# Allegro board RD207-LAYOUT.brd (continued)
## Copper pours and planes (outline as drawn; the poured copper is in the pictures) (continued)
N17056068 on TOP: 49.06,31 49,31.01 48.96,31.04 47.75,32.25 47.52,32.38 47.39,32.4 46.15,32.4 46.04,32.44 46,32.55 46,32.8 45.82,33.22 45.4,33.4 44.6,33.4 44.18,33.22 44,32.8 44,32.55 43.96,32.44 43.85,32.4 42.55,32.4 42.44,32.44 42.4,32.55 42.4,33.6 42.44,33.71 42.55,33.75 43.2,33.75 43.6,33.86 43.89,34.15 44,34.55 44,36.1 44.04,36.21 44.15,36.25 45.54,36.25 46.12,36.36 46.6,36.69 48.81,38.9 48.82,38.9 49,39.13 49.13,39.38 49.15,39.41 49.22,39.55 49.25,39.71 49.25,42.7 49.4,43.05 49.75,43.2 53.5,43.2 53.85,43.05 54,42.7 54,38.23 53.94,38.11 53.82,38.08 53.73,38.1 53.65,38.1 53.05,38.1 52.48,37.87 52.25,37.3 52.25,34.7 52.48,34.13 53.05,33.9 53.65,33.9 53.73,33.9 53.82,33.92 53.94,33.89 54,33.77 54,31.5 53.85,31.15 53.5,31
N17156262 on TOP: 20.75,68.1 20.66,68.12 20.58,68.17 17.91,70.84 17.83,70.95 17.76,71.2 17.76,79.5 17.83,79.75 18.01,79.93 18.26,80 25.6,80 25.85,79.93 26.03,79.75 26.1,79.5 26.1,71.15 26.02,70.97 25.84,70.9 25.8,70.9 25.6,70.9 25.03,70.67 24.8,70.1 24.8,69.9 25.03,69.33 25.6,69.1 25.8,69.1 25.84,69.1 26.02,69.03 26.1,68.85 26.1,68.6 26.03,68.35 25.85,68.17 25.6,68.1
N17207036 on TOP: 143.54,117.04 143.54,117.08 143.65,117.18 143.8,117.15 143.95,117 143.99,116.89 143.95,116.78 143.8,116.63 143.76,116.61 143.61,116.61 143.54,116.74
N17207036 on TOP: 142.24,115.58 142.22,115.62 142.22,115.77 142.35,115.84 142.65,115.84 142.69,115.84 142.79,115.73 142.76,115.58 142.61,115.43 142.5,115.39 142.39,115.43
N17207166 on TOP: 138.97,115.59 138.95,115.63 138.95,115.78 139.08,115.85 139.38,115.85 139.42,115.85 139.52,115.74 139.49,115.59 139.34,115.44 139.23,115.4 139.12,115.44
N17209635 on TOP: 395.97,234.09 395.95,234.13 395.95,234.28 396.08,234.35 396.38,234.35 396.42,234.35 396.52,234.24 396.49,234.09 396.34,233.94 396.23,233.9 396.12,233.94
N17227344 on TOP (solid shape): 361.53,117.8 362.08,117.55 362.13,116.95 361.95,116.37 361.36,116.24 360.47,116.53 360.06,117.16 360.59,117.7
N17229013 on TOP (solid shape): 361.53,37.3 362.08,37.05 362.13,36.45 361.95,35.87 361.36,35.74 360.47,36.03 360.06,36.66 360.59,37.2
N17284402 on TOP: 284.2,235.59 279.62,238.45 279.59,238.45 271.37,238.45 271.24,238.47 271.01,238.6 270.68,238.93 270.63,239.01 270.61,239.1 270.61,255.4 270.63,255.49 270.68,255.57 280.11,265 280.21,265.07 280.46,265.14 304.24,265.14 304.37,265.12 304.6,265 314.45,255.14 345.83,255.14 346.22,255.06 346.54,254.85 346.76,254.52 346.83,254.14 346.83,249.03 346.82,248.97 346.45,247.92 346.33,246.87 346.33,245 346.25,244.61 346.04,244.29 345.7,244.07 345.33,244 315.95,244 298.35,226.4 298.24,226.32 297.99,226.25 291.23,226.25 291.14,226.27 291.06,226.31 290.33,226.85 289.51,227.24 289.37,227.36 289.36,227.54 287.77,229.65 286.18,227.54 286.17,227.36 286.03,227.24 285.58,227.04 285.14,226.8 285.08,226.77 285.01,226.77 284.21,226.77 284.08,226.78 283.85,226.91 283.54,227.23 283.51,227.26 283.48,227.31 283.46,227.4 283.45,227.5 283.45,230.07 283.46,230.15 283.5,230.23 ; 3 cut-outs
N17284406 on TOP: 346.25,80.61 346.04,80.29 345.7,80.07 345.33,80 315.95,80 298.35,62.4 298.18,62.29 297.99,62.25 291.23,62.25 291.14,62.27 291.06,62.31 290.33,62.85 289.51,63.24 289.37,63.36 289.36,63.54 287.77,65.65 286.18,63.54 286.17,63.36 286.03,63.24 285.54,63.03 285.08,62.76 285.01,62.73 284.94,62.72 284.21,62.72 284.08,62.74 283.85,62.87 283.84,62.88 283.76,62.98 283.7,63.23 283.7,66.39 283.71,66.47 283.74,66.54 284.09,71.8 279.54,74.45 279.5,74.45 271.37,74.45 271.24,74.47 271.01,74.6 270.68,74.93 270.63,75.01 270.61,75.1 270.61,91.4 270.63,91.49 270.68,91.57 280.1,100.99 280.11,101 280.27,101.1 280.46,101.14 281.64,101.14 282.16,101.08 282.64,101.07 282.66,101.07 283.14,101.08 283.66,101.14 304.24,101.14 304.43,101.1 304.6,101 314.45,91.14 345.83,91.14 346.54,90.85 346.83,90.14 346.83,85.03 346.82,84.97 346.45,83.92 346.33,82.87 346.33,81 ; 3 cut-outs
N17284446 on TOP: 77.95,106.8 77.84,106.84 77.8,106.95 77.8,129.5 77.87,129.75 78.05,129.93 78.3,130 83.5,130 83.75,129.93 83.93,129.75 84,129.5 84,127.84 83.81,127.03 83.75,126.25 83.75,125.89 83.74,125.83 83.71,125.78 83.41,125.48 82.4,123.97 82.04,122.19 82.04,120.41 81.96,119.91 81.94,119.44 81.94,118.34 81.96,117.87 82.04,117.37 82.04,116.59 82.4,114.81 83.41,113.3 83.96,112.75 83.99,112.7 84,112.64 84,109.2 83.93,108.95 83.75,108.77 83.5,108.7 82.86,108.7 82.61,108.63 82.5,108.55 81.04,107.09 80.71,106.87 80.34,106.8
N17284446 on BOTTOM: 79,108 78.61,108.08 78.29,108.29 78.07,108.63 78,109 78,129.5 78.07,129.75 78.25,129.93 78.5,130 83.5,130 83.75,129.93 83.93,129.75 84,129.5 84,108.5 83.93,108.25 83.75,108.07 83.5,108
N17284446 on CONDUCTIVE2: 79,108 78.61,108.08 78.29,108.29 78.07,108.63 78,109 78,129.5 78.07,129.75 78.25,129.93 78.5,130 83.5,130 83.75,129.93 83.93,129.75 84,129.5 84,109 83.92,108.61 83.71,108.29 83.37,108.07 83,108
N17284446 on CONDUCTIVE3: 191,251.79 191.04,251.98 191.15,252.15 195.35,256.35 195.35,256.35 195.52,256.46 195.71,256.5 206.15,256.5 206.24,256.48 206.32,256.43 211.35,251.4 211.43,251.29 211.5,251.04 211.5,143.46 211.48,143.33 211.35,143.1 203.82,135.57 203.79,135.55 203.76,135.53 203.7,135.51 203.65,135.5 144.85,135.5 144.76,135.52 144.68,135.57 143.4,136.85 143.17,136.98 143.04,137 91.62,137 91.55,136.95 91.46,136.94 91.39,136.94 91.14,136.87 91.04,136.79 84.15,129.9 84.02,129.67 84,129.54 84,109 83.92,108.61 83.71,108.29 83.37,108.07 83,108 79,108 78.61,108.08 78.29,108.29 78.07,108.63 78,109 78,140.29 78.02,140.42 78.15,140.65 83.35,145.85 83.52,145.96 83.71,146 91.63,146 91.76,145.98 91.88,145.93 116.82,145.93 117.02,145.97 117.18,146.08 119.93,148.83 120.01,148.88 120.1,148.9 185,148.9 190.85,154.75 190.96,154.92 191,155.11 ; 2 cut-outs
N17284506 on BOTTOM (solid shape): 371.5,296.25 372.23,295.65 372.43,294.69 372.21,294 371.5,293.82 370.79,294 370.57,294.69 370.77,295.65
N17284506 on BOTTOM (solid shape): 372.21,297 372.43,296.31 372.23,295.35 371.5,294.75 370.77,295.35 370.57,296.31 370.56,296.38 370.55,296.46 370.77,296.99 371.3,297.21 371.4,297.2 371.5,297.18
N17284767 on TOP: 126.95,106.8 126.84,106.84 126.8,106.95 126.8,129.25 126.88,129.64 127.09,129.96 127.43,130.18 127.8,130.25 134,130.25 134.39,130.17 134.71,129.96 134.93,129.62 135,129.25 135,126.66 135,126.63 134.9,125.95 134.9,125.26 134.89,125.2 134.86,125.14 134.41,124.69 133.4,123.18 133.04,121.4 133.04,120.41 132.96,119.91 132.94,119.44 132.94,116.18 132.93,116.13 132.08,114.65 131.79,113.01 131.79,111.03 131.79,110.9 131.79,110.87 131.78,110.84 131.53,109.99 131.44,109.1 131.44,108.55 131.43,108.49 131.4,108.45 130.04,107.09 129.71,106.87 129.34,106.8
N17284767 on BOTTOM: 128,113 127.61,113.08 127.29,113.29 127.07,113.63 127,114 127,131.5 127.08,131.89 127.29,132.21 127.63,132.43 128,132.5 133.89,132.5 134.28,132.42 134.6,132.21 134.82,131.87 134.89,131.5 134.89,118.95 134.81,118.57 134.6,118.25 129.64,113.29 129.32,113.08 128.94,113
N17284767 on CONDUCTIVE2: 193.35,170 193.39,170.2 193.5,170.36 198.49,175.35 198.65,175.46 198.85,175.5 207.2,175.5 207.29,175.48 207.37,175.43 209.55,173.25 209.66,173.08 209.7,172.89 209.7,135 209.55,134.65 209.2,134.5 143.92,134.5 143.83,134.52 143.75,134.57 140.5,135.99 137.13,134.9 135.74,133.17 135.25,131 135.25,130.21 135.23,130.08 135.1,129.85 134.89,129.64 134.89,115.53 134.87,115.44 134.82,115.36 134.21,114.76 133.47,113.8 133,112.68 132.91,112.55 132.76,112.5 127.25,112.5 127.07,112.57 127,112.75 127,140.79 127.04,140.98 127.15,141.15 133.43,147.43 133.51,147.48 133.6,147.5 190.74,147.5 190.93,147.54 191.1,147.65 193.2,149.75 193.31,149.92 193.35,150.11 ; 1 cut-out
N17284767 on CONDUCTIVE3: 127.5,113.25 127.25,113.32 127.07,113.5 127,113.75 127,131.5 127.08,131.89 127.29,132.21 127.63,132.43 128,132.5 134,132.5 134.71,132.21 135,131.5 135,119.06 134.92,118.68 134.71,118.36 129.75,113.4 129.64,113.32 129.39,113.25
N17284780 on TOP: 284.33,144.63 284.1,144.76 283.82,145.04 283.74,145.14 283.67,145.39 283.67,148.36 283.69,148.44 283.72,148.51 284.1,153.78 279.54,156.45 279.5,156.45 271.62,156.45 271.49,156.47 271.26,156.6 270.68,157.18 270.63,157.26 270.61,157.35 270.61,173.4 270.63,173.49 270.68,173.57 279.96,182.85 279.96,182.85 280.12,182.96 280.31,183 304.49,183 304.59,182.98 304.67,182.92 314.45,173.14 333.9,173.14 345.83,173.14 346.54,172.85 346.83,172.14 346.83,167.03 346.82,166.97 346.45,165.92 346.33,164.87 346.33,163 346.25,162.61 346.04,162.29 345.7,162.07 345.33,162 315.95,162 298.35,144.4 298.18,144.29 297.99,144.25 291.23,144.25 291.14,144.27 291.06,144.31 290.33,144.85 289.51,145.24 289.37,145.36 289.36,145.54 287.77,147.65 286.18,145.54 286.17,145.36 286.03,145.24 285.45,144.98 284.91,144.65 284.85,144.62 284.77,144.61 284.46,144.61 ; 3 cut-outs
N17285107 on TOP: 198,84 197.29,84.29 197,85 197,101.29 196.96,101.48 196.85,101.65 191.85,106.65 191.62,106.78 191.49,106.8 183.43,106.8 183.34,106.84 183.3,106.92 183.3,111.59 183.34,111.78 183.45,111.95 185.35,113.85 185.46,113.93 185.71,114 196.29,114 196.42,113.98 196.65,113.85 202.35,108.15 202.46,107.99 202.5,107.79 202.5,90.8 202.21,90.09 201.5,89.8 200.5,89.8 198.7,88 200.5,86.2 200.75,86.2 200.93,86.13 201,85.95 201,85 200.71,84.29 200,84
N17285107 on BOTTOM: 198,84 197.61,84.08 197.29,84.29 197.07,84.63 197,85 197,101.29 196.93,101.54 196.85,101.65 191.9,106.6 191.73,106.71 191.54,106.75 184.3,106.75 183.59,107.04 183.3,107.75 183.3,111.59 183.34,111.78 183.45,111.95 184.52,112.96 184.71,113 197.29,113 197.48,112.96 197.65,112.85 202.46,107.98 202.5,107.79 202.5,91 202.42,90.61 202.21,90.29 201.87,90.07 201.5,90 200.5,90 198.5,88 200.5,86 200.75,86 200.93,85.93 201,85.75 201,85 200.92,84.61 200.71,84.29 200.37,84.07 200,84
N17285107 on CONDUCTIVE2, CONDUCTIVE3: 197,101.29 196.96,101.48 196.85,101.65 191.15,107.35 190.98,107.46 190.79,107.5 184.5,107.5 184.11,107.58 183.79,107.79 183.57,108.13 183.5,108.5 183.5,111.59 183.58,111.98 183.79,112.29 185.21,113.71 185.54,113.93 185.91,114 196.09,114 196.48,113.92 196.79,113.71 203.85,106.65 203.93,106.54 204,106.29 204,85 203.71,84.29 203,84 198,84 197.29,84.29 197,85 ; 1 cut-out
N17285634 on TOP: 412.54,105.39 412.5,105.5 412.54,105.61 412.69,105.76 412.73,105.78 412.88,105.78 412.95,105.65 412.95,105.35 412.95,105.31 412.84,105.21 412.69,105.24
N17285636 on TOP: 413.85,108.45 414,108.6 414.15,108.45 414.24,108.24 414.45,108.15 414.6,108 414.45,107.85 414.24,107.76 414.15,107.55 414,107.4 413.85,107.55

Small or netless copper shapes (teardrops, artwork), in the pictures only: 1163 on TOP, 77 on BOTTOM, 6 on CONDUCTIVE2, 5 on CONDUCTIVE3

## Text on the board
Ref Des/Silkscreen Top: SN
SYMBOL-1-TOP: TP4 | C10 | R3 | C20 | R10 | R8 | ZD1 | R11 | F2 | ZNR2 | 1 | LED1 | ZNR3 | F3 | C19 | CN1 | 2 | R12 | TP5 | C22 | C3 | TP8 | TP6 | TP7 | R13 | F1 | R139 | TP50 | C120 | C23 | C119 | R140 | C1 | TP9 | D1 | LED2 | R2 | R1 | PS2 | ZNR1 | TP1 | C47 | R21 | C2 | C46 | R19 | IC31 | C24 | C25 | 8 | TP51 | CT1 | C143 | L1 | R80 | C86 | L14 | IC16 | R147 | C152 | C121 | C140 | R77 | R75 | IC28 | R72 | R78 | TP32 | C122 | R146 | IC17 | C151 | C85 | IC8 | C4 | C93 | C6 | R4 | R6 | C8 | D2 | C141 | R28 | C54 | R31 | C57 | CT2 | IC33 | C35 | C37 | C125 | L15 | IC9 | R149 | C154 | C123 | TP2 | R95 | C91 | R7 | L11 | C11 | IC18 | R5 | C124 | R92 | R148 | C153 | C5 | IC19 | TP37 | C89 | R91 | TP33 | TP52 | C98 | R90 | C99 | R89 | TP35 | L2 | R144 | C94 | C95 | TP53 | R88 | C7 | C9 | IC30 | C12 | D3 | R9 | R27 | C55 | CT3 | R29 | C56 | C39 | C38 | IC35 | IC36 | TP3 | L8 | L4 | L6 | L5 | L9 | L7 | C80 | C64 | R70 | R57 | D12 | D13 | D14 | D15 | D16 | R44 | D11 | C72 | R37 | R50 | R63 | R42 | R55 | R68 | R41 | R49 | R56 | R36 | R54 | R62 | R69 | R67 | 7 | TP16 | TP17 | TP19 | TP18 | TP22 | TP24 | TP29 | TP28 | TP23 | TP21 | TP27 | TP26 | R43 | PS3 | PS4 | PS5 | C78 | C62 | C70 | IC12 | L16 | C42 | R106 | C32 | TP46 | TP49 | TP48 | TP47 | TP44 | TP45 | R102 | C104 | R110 | IC15 | R109 | TP38 | C117 | IC22 | TP39 | IC13 | L17 | C126 | C52 | R24 | R125 | C109 | R22 | C127 | IC2 | R138 | 20 | R127 | TP41 | C48 | R122 | C33 | C43 | R137 | R136 | R135 | R134 | R133 | R132 | TP40 | C53 | CN8 | R121 | D10 | R20 | TP54 | TP43 | TP10 | IC24 | IC23 | C129 | R120 | C128 | R119 | R145 | C111 | C112 | C113 | TP42 | TP55 | 3 | TB2 | TB1 | TB3 | TB4 | PS1 | 4 | C15 | C21 | L3 | C13 | 5 | Q7 | R143 | RLY1 | PC7 | R18 | R141 | R23 | R142 | C14 | TP13 | IC32 | C144 | R86 | TP31 | TP62 | L10 | R84 | R82 | R83 | R79 | R81 | D17 | R76 | R73 | C84 | C17 | C51 | TP36 | TP12 | IC10 | RLY2 | IC1 | C50 | TP11 | TP63 | IC29 | R30 | TP14 | R25 | C16 | IC34 | IC20 | C147 | TP34 | C146 | TP56 | R99 | R101 | R98 | R96 | R97 | D18 | R93 | C88 | C96 | C97 | R87 | C18 | PS6 | C142 | TP64 | RLY3 | R32 | R26 | TP15 | C150 | C149 | A | D7 | D6 | D8 | D4 | D5 | D9 | C | Q6 | Q4 | Q5 | Q3 | Q2 | Q1 | D | R71 | C67 | C59 | C69 | C75 | R58 | C61 | C77 | R45 | C79 | S | G | C63 | C71 | IC6 | IC4 | IC5 | R34 | R39 | R47 | R60 | R52 | R65 | C58 | C66 | C74 | C73 | C65 | C60 | C68 | C76 | C81 | 6 | TP25 | TP30 | TP20 | PC4 | PC5 | PC6 | PC1 | PC2 | PC3 | R40 | R38 | R35 | R33 | R48 | R46 | R53 | R51 | R61 | R59 | R66 | R64 | R113 | R111 | R108 | R114 | C101 | R116 | R112 | R104 | D19 | R115 | R105 | L12 | C105 | R107 | R103 | C102 | C103 | IC14 | R129 | R131 | IC21 | C110 | R128 | C108 | D20 | C118 | R124 | L13 | R130 | R123 | C106 | R126 | C107 | CN9 | PS7 | R117 | R118 | TB5 | TB6 | C116 | C115 | C114 | 60 | 59 | FG | 24V | 5V | GND | W | V | U | N | P | HSP0256-B00-0001B
SYMBOL-1-BOTTOM: 1 | 2 | C26 | C27 | C36 | C34 | C28 | C29 | C40 | C41 | C31 | C30 | C45 | C44 | CN2 | CN7 | CN6 | CN4 | CN5 | CN3 | R14 | R15 | R16 | R17 | D | S | G
